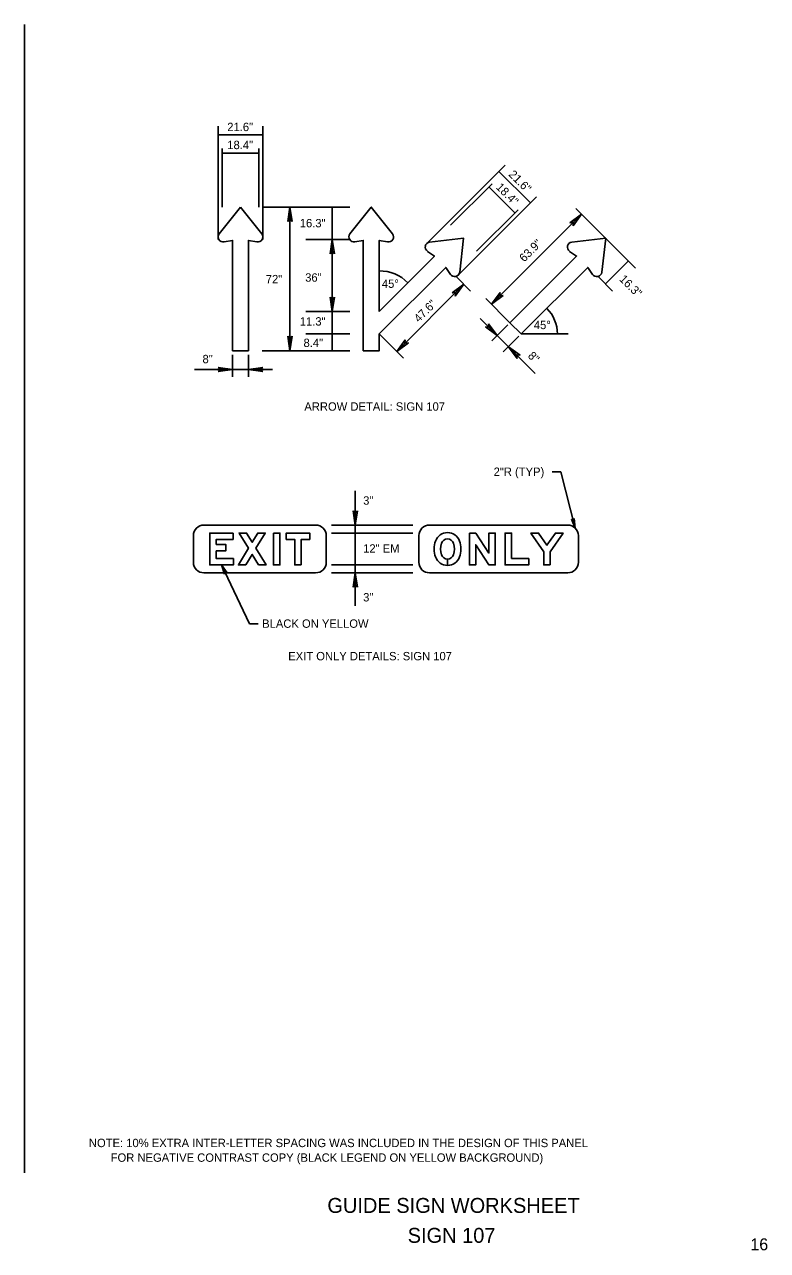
# Model space of a CAD drawing. Extents: x 531799 to 532094, y 1531149 to 1533620.
# Drawn here: x 531879.4 to 531932.2, y 1531151.4 to 1531238.5 of the extents above; entities that cross this region are included whole.
import ezdxf

# ---------------------------------------------------------------- set-up
doc = ezdxf.new("R2010")
doc.units = 0
for name, color, linetype in [('GSBWFill', 7, 'Continuous'), ('GSColorFill', 7, 'Continuous'), ('GSDims', 7, 'Continuous'), ('GSOutline', 7, 'Continuous'), ('LeaderLine_dp', 7, 'Continuous'), ('SheetBorder_dp', 7, 'Continuous'), ('SignPanel', 7, 'Continuous'), ('TextLabel', 7, 'Continuous'), ('TextMisc', 7, 'Continuous'), ('TextShtNo', 7, 'Continuous')]:
    doc.layers.add(name, color=color, linetype=linetype)

msp = doc.modelspace()

# ---------------------------------------------------------------- linework, layer by layer
at = {"layer": 'GSBWFill'}
for p, q in [((531892.157, 1531202.947), (531900.088, 1531202.947)), ((531917.996, 1531202.947), (531908.176, 1531202.947)), ((531891.401, 1531200.304), (531891.401, 1531202.192)), ((531900.844, 1531202.192), (531900.844, 1531200.304)), ((531907.421, 1531202.192), (531907.421, 1531200.304)), ((531918.751, 1531200.304), (531918.751, 1531202.192)), ((531909.458, 1531200.075), (531909.458, 1531200.528)), ((531909.458, 1531200.528), (531909.458, 1531200.075)), ((531900.088, 1531199.548), (531892.157, 1531199.548)), ((531908.176, 1531199.548), (531917.996, 1531199.548))]:
    msp.add_line(p, q, dxfattribs=at)
for points in [[(531894.227, 1531202.381), (531894.227, 1531201.928), (531893.026, 1531201.928), (531893.026, 1531201.565), (531893.705, 1531201.565), (531893.705, 1531201.112), (531893.026, 1531201.112), (531893.026, 1531200.568), (531894.249, 1531200.568), (531894.249, 1531200.115), (531892.572, 1531200.115), (531892.572, 1531202.381)], [(531896.039, 1531200.115), (531895.584, 1531200.859), (531895.129, 1531200.115), (531894.598, 1531200.115), (531895.319, 1531201.294), (531894.655, 1531202.381), (531895.186, 1531202.381), (531895.584, 1531201.729), (531895.982, 1531202.381), (531896.513, 1531202.381), (531895.85, 1531201.294), (531896.57, 1531200.115)], [(531897.094, 1531202.381), (531897.547, 1531202.381), (531897.547, 1531200.115), (531897.094, 1531200.115)], [(531899.061, 1531200.115), (531898.608, 1531200.115), (531898.608, 1531201.928), (531897.996, 1531201.928), (531897.996, 1531202.381), (531899.673, 1531202.381), (531899.673, 1531201.928), (531899.061, 1531201.928)], [(531911.012, 1531202.381), (531911.465, 1531202.381), (531912.394, 1531200.953), (531912.394, 1531202.381), (531912.847, 1531202.381), (531912.847, 1531200.115), (531912.399, 1531200.115), (531911.465, 1531201.55), (531911.465, 1531200.115), (531911.012, 1531200.115)], [(531914.003, 1531200.568), (531915.226, 1531200.568), (531915.226, 1531200.115), (531913.549, 1531200.115), (531913.549, 1531202.381), (531914.003, 1531202.381)], [(531916.748, 1531200.115), (531916.295, 1531200.115), (531916.295, 1531201.044), (531915.377, 1531202.381), (531915.926, 1531202.381), (531916.521, 1531201.515), (531917.116, 1531202.381), (531917.666, 1531202.381), (531916.748, 1531201.044)]]:
    msp.add_lwpolyline(points, close=True, dxfattribs=at)
for centre, radius, start, end in [((531892.157, 1531202.192), 0.755, 90, 180), ((531900.088, 1531202.192), 0.755, 0, 90), ((531908.176, 1531202.192), 0.755, 90, 180), ((531917.996, 1531202.192), 0.755, 0, 90), ((531909.458, 1531201.506), 0.906, 19.60625, 160.39375), ((531910.195, 1531201.244), 1.688, 160.39375, 199.60625), ((531910.195, 1531201.244), 1.235, 160.39375, 199.60625), ((531909.458, 1531201.506), 0.453, 19.60625, 160.39375), ((531908.722, 1531201.244), 1.235, 340.39375, 19.60625), ((531908.722, 1531201.244), 1.688, 340.39375, 19.60625), ((531892.157, 1531200.304), 0.755, 180, 270), ((531900.088, 1531200.304), 0.755, 270, 0), ((531908.176, 1531200.304), 0.755, 180, 270), ((531909.458, 1531200.982), 0.906, 199.60625, 270), ((531909.458, 1531200.982), 0.453, 199.60625, 270), ((531909.458, 1531200.982), 0.453, 270.01433, 340.39375), ((531909.458, 1531200.982), 0.906, 270.00716, 340.39375), ((531917.996, 1531200.304), 0.755, 270, 0)]:
    msp.add_arc(centre, radius, start, end, dxfattribs=at)
at = {"layer": 'GSColorFill'}
for p, q in [((531909.458, 1531200.075), (531909.458, 1531200.528)), ((531909.458, 1531200.528), (531909.458, 1531200.075))]:
    msp.add_line(p, q, dxfattribs=at)
for points in [[(531894.227, 1531202.381), (531894.227, 1531201.928), (531893.026, 1531201.928), (531893.026, 1531201.565), (531893.705, 1531201.565), (531893.705, 1531201.112), (531893.026, 1531201.112), (531893.026, 1531200.568), (531894.249, 1531200.568), (531894.249, 1531200.115), (531892.572, 1531200.115), (531892.572, 1531202.381)], [(531896.039, 1531200.115), (531895.584, 1531200.859), (531895.129, 1531200.115), (531894.598, 1531200.115), (531895.319, 1531201.294), (531894.655, 1531202.381), (531895.186, 1531202.381), (531895.584, 1531201.729), (531895.982, 1531202.381), (531896.513, 1531202.381), (531895.85, 1531201.294), (531896.57, 1531200.115)], [(531897.094, 1531202.381), (531897.547, 1531202.381), (531897.547, 1531200.115), (531897.094, 1531200.115)], [(531899.061, 1531200.115), (531898.608, 1531200.115), (531898.608, 1531201.928), (531897.996, 1531201.928), (531897.996, 1531202.381), (531899.673, 1531202.381), (531899.673, 1531201.928), (531899.061, 1531201.928)], [(531911.012, 1531202.381), (531911.465, 1531202.381), (531912.394, 1531200.953), (531912.394, 1531202.381), (531912.847, 1531202.381), (531912.847, 1531200.115), (531912.399, 1531200.115), (531911.465, 1531201.55), (531911.465, 1531200.115), (531911.012, 1531200.115)], [(531914.003, 1531200.568), (531915.226, 1531200.568), (531915.226, 1531200.115), (531913.549, 1531200.115), (531913.549, 1531202.381), (531914.003, 1531202.381)], [(531916.748, 1531200.115), (531916.295, 1531200.115), (531916.295, 1531201.044), (531915.377, 1531202.381), (531915.926, 1531202.381), (531916.521, 1531201.515), (531917.116, 1531202.381), (531917.666, 1531202.381), (531916.748, 1531201.044)]]:
    msp.add_lwpolyline(points, close=True, dxfattribs=at)
for centre, radius, start, end in [((531909.458, 1531201.506), 0.906, 19.60625, 160.39375), ((531910.195, 1531201.244), 1.688, 160.39375, 199.60625), ((531910.195, 1531201.244), 1.235, 160.39375, 199.60625), ((531909.458, 1531201.506), 0.453, 19.60625, 160.39375), ((531908.722, 1531201.244), 1.235, 340.39375, 19.60625), ((531908.722, 1531201.244), 1.688, 340.39375, 19.60625), ((531909.458, 1531200.982), 0.906, 199.60625, 270), ((531909.458, 1531200.982), 0.453, 199.60625, 270), ((531909.458, 1531200.982), 0.453, 270.01433, 340.39375), ((531909.458, 1531200.982), 0.906, 270.00716, 340.39375)]:
    msp.add_arc(centre, radius, start, end, dxfattribs=at)
at = {"layer": 'GSOutline'}
for points in [[(531894.227, 1531202.381), (531894.227, 1531201.928), (531893.026, 1531201.928), (531893.026, 1531201.565), (531893.705, 1531201.565), (531893.705, 1531201.112), (531893.026, 1531201.112), (531893.026, 1531200.568), (531894.249, 1531200.568), (531894.249, 1531200.115), (531892.572, 1531200.115), (531892.572, 1531202.381)], [(531896.039, 1531200.115), (531895.584, 1531200.859), (531895.129, 1531200.115), (531894.598, 1531200.115), (531895.319, 1531201.294), (531894.655, 1531202.381), (531895.186, 1531202.381), (531895.584, 1531201.729), (531895.982, 1531202.381), (531896.513, 1531202.381), (531895.85, 1531201.294), (531896.57, 1531200.115)], [(531897.094, 1531202.381), (531897.547, 1531202.381), (531897.547, 1531200.115), (531897.094, 1531200.115)], [(531899.061, 1531200.115), (531898.608, 1531200.115), (531898.608, 1531201.928), (531897.996, 1531201.928), (531897.996, 1531202.381), (531899.673, 1531202.381), (531899.673, 1531201.928), (531899.061, 1531201.928)], [(531911.012, 1531202.381), (531911.465, 1531202.381), (531912.394, 1531200.953), (531912.394, 1531202.381), (531912.847, 1531202.381), (531912.847, 1531200.115), (531912.399, 1531200.115), (531911.465, 1531201.55), (531911.465, 1531200.115), (531911.012, 1531200.115)], [(531914.003, 1531200.568), (531915.226, 1531200.568), (531915.226, 1531200.115), (531913.549, 1531200.115), (531913.549, 1531202.381), (531914.003, 1531202.381)], [(531916.748, 1531200.115), (531916.295, 1531200.115), (531916.295, 1531201.044), (531915.377, 1531202.381), (531915.926, 1531202.381), (531916.521, 1531201.515), (531917.116, 1531202.381), (531917.666, 1531202.381), (531916.748, 1531201.044)]]:
    msp.add_lwpolyline(points, close=True, dxfattribs=at)
for centre, radius, start, end in [((531909.458, 1531201.506), 0.906, 19.60625, 160.39375), ((531910.195, 1531201.244), 1.688, 160.39375, 199.60625), ((531910.195, 1531201.244), 1.235, 160.39375, 199.60625), ((531909.458, 1531201.506), 0.453, 19.60625, 160.39375), ((531908.722, 1531201.244), 1.235, 340.39375, 19.60625), ((531908.722, 1531201.244), 1.688, 340.39375, 19.60625), ((531909.458, 1531200.982), 0.906, 199.60625, 340.39375), ((531909.458, 1531200.982), 0.453, 199.60625, 340.39375)]:
    msp.add_arc(centre, radius, start, end, dxfattribs=at)
at = {"layer": 'LeaderLine_dp'}
for p, q in [((531893.165, 1531223.222), (531893.165, 1531231.279)), ((531896.334, 1531223.222), (531896.334, 1531231.279)), ((531893.165, 1531230.656), (531896.334, 1531230.656)), ((531893.447, 1531225.53), (531893.447, 1531229.697)), ((531893.447, 1531229.376), (531896.053, 1531229.376)), ((531896.053, 1531225.53), (531896.053, 1531229.697)), ((531907.848, 1531222.811), (531913.545, 1531228.509)), ((531913.105, 1531228.068), (531915.346, 1531225.827)), ((531909.68, 1531224.245), (531912.626, 1531227.191)), ((531912.399, 1531226.964), (531914.241, 1531225.121)), ((531902.506, 1531225.53), (531896.334, 1531225.53)), ((531898.107, 1531224.511), (531898.26, 1531225.53)), ((531898.26, 1531215.333), (531898.26, 1531225.53)), ((531898.26, 1531225.53), (531898.413, 1531224.511)), ((531901.268, 1531223.222), (531901.268, 1531225.53)), ((531910.089, 1531220.57), (531915.787, 1531226.268)), ((531898.26, 1531224.715), (531898.107, 1531224.511)), ((531898.413, 1531224.511), (531898.26, 1531224.715)), ((531911.522, 1531222.402), (531914.468, 1531225.348)), ((531912.584, 1531218.633), (531918.984, 1531225.032)), ((531918.155, 1531224.419), (531918.984, 1531225.032)), ((531918.984, 1531225.032), (531918.371, 1531224.203)), ((531918.578, 1531225.438), (531922.811, 1531221.205)), ((531918.407, 1531224.455), (531918.155, 1531224.419)), ((531918.371, 1531224.203), (531918.407, 1531224.455)), ((531902.506, 1531223.222), (531899.393, 1531223.222)), ((531901.115, 1531222.202), (531901.268, 1531223.222)), ((531901.268, 1531218.123), (531901.268, 1531223.222)), ((531901.268, 1531223.222), (531901.421, 1531222.202)), ((531901.268, 1531222.406), (531901.115, 1531222.202)), ((531901.421, 1531222.202), (531901.268, 1531222.406)), ((531920.672, 1531220.079), (531922.305, 1531221.711)), ((531910.089, 1531220.57), (531911.086, 1531219.573)), ((531920.181, 1531220.57), (531921.178, 1531219.573)), ((531905.846, 1531215.28), (531910.613, 1531220.047)), ((531909.783, 1531219.434), (531910.613, 1531220.047)), ((531910.036, 1531219.47), (531909.783, 1531219.434)), ((531910.613, 1531220.047), (531910, 1531219.218)), ((531910, 1531219.218), (531910.036, 1531219.47)), ((531912.584, 1531218.633), (531913.197, 1531219.462)), ((531913.197, 1531219.462), (531913.161, 1531219.209)), ((531901.268, 1531218.123), (531901.115, 1531219.143)), ((531901.115, 1531219.143), (531901.268, 1531218.939)), ((531901.268, 1531218.939), (531901.421, 1531219.143)), ((531901.421, 1531219.143), (531901.268, 1531218.123)), ((531912.179, 1531219.038), (531913.894, 1531217.323)), ((531913.414, 1531219.246), (531912.584, 1531218.633)), ((531913.161, 1531219.209), (531913.414, 1531219.246)), ((531902.506, 1531218.123), (531899.393, 1531218.123)), ((531901.268, 1531215.333), (531901.268, 1531218.123)), ((531911.777, 1531217.631), (531912.989, 1531216.418)), ((531912.412, 1531216.995), (531912.16, 1531217.031)), ((531912.16, 1531217.031), (531912.989, 1531216.418)), ((531912.989, 1531216.418), (531912.376, 1531217.248)), ((531912.376, 1531217.248), (531912.412, 1531216.995)), ((531912.613, 1531216.042), (531913.733, 1531217.163)), ((531898.26, 1531215.333), (531898.107, 1531216.353)), ((531898.107, 1531216.353), (531898.26, 1531216.149)), ((531898.26, 1531216.149), (531898.413, 1531216.353)), ((531898.413, 1531216.353), (531898.26, 1531215.333)), ((531902.506, 1531216.521), (531899.393, 1531216.521)), ((531904.604, 1531216.522), (531906.319, 1531214.806)), ((531905.846, 1531215.28), (531906.458, 1531216.109)), ((531906.458, 1531216.109), (531906.422, 1531215.857)), ((531912.989, 1531216.418), (531913.79, 1531215.617)), ((531913.414, 1531215.241), (531914.534, 1531216.361)), ((531914.695, 1531216.522), (531918.025, 1531216.522)), ((531894.183, 1531213.465), (531894.183, 1531215.049)), ((531895.316, 1531213.465), (531895.316, 1531215.049)), ((531902.506, 1531215.333), (531896.279, 1531215.333)), ((531906.675, 1531215.893), (531905.846, 1531215.28)), ((531906.422, 1531215.857), (531906.675, 1531215.893)), ((531913.79, 1531215.617), (531915.692, 1531213.715)), ((531913.79, 1531215.617), (531914.403, 1531214.788)), ((531914.619, 1531215.004), (531913.79, 1531215.617)), ((531914.403, 1531214.788), (531914.367, 1531215.04)), ((531914.367, 1531215.04), (531914.619, 1531215.004)), ((531894.183, 1531213.997), (531891.493, 1531213.997)), ((531893.367, 1531213.997), (531893.163, 1531214.15)), ((531893.163, 1531214.15), (531894.183, 1531213.997)), ((531894.183, 1531213.997), (531893.163, 1531213.844)), ((531893.163, 1531213.844), (531893.367, 1531213.997)), ((531895.316, 1531213.997), (531894.183, 1531213.997)), ((531895.316, 1531213.997), (531896.336, 1531214.15)), ((531897.03, 1531213.997), (531895.316, 1531213.997)), ((531896.336, 1531213.844), (531895.316, 1531213.997)), ((531896.336, 1531214.15), (531896.132, 1531213.997)), ((531896.132, 1531213.997), (531896.336, 1531213.844)), ((531902.902, 1531205.367), (531902.902, 1531202.947)), ((531902.902, 1531202.947), (531902.749, 1531203.967)), ((531902.749, 1531203.967), (531902.902, 1531203.763)), ((531902.902, 1531203.763), (531903.055, 1531203.967)), ((531903.055, 1531203.967), (531902.902, 1531202.947)), ((531901.212, 1531202.947), (531906.993, 1531202.947)), ((531902.902, 1531202.947), (531902.902, 1531199.548)), ((531918.396, 1531203.253), (531918.264, 1531203.36)), ((531918.264, 1531203.36), (531918.53, 1531202.726)), ((531918.462, 1531203.41), (531918.396, 1531203.253)), ((531918.53, 1531202.726), (531918.462, 1531203.41)), ((531901.212, 1531202.381), (531906.993, 1531202.381)), ((531893.411, 1531200.115), (531893.793, 1531199.543)), ((531893.608, 1531199.456), (531893.411, 1531200.115)), ((531893.642, 1531199.623), (531893.608, 1531199.456)), ((531893.793, 1531199.543), (531893.642, 1531199.623)), ((531901.212, 1531200.115), (531906.993, 1531200.115)), ((531901.212, 1531199.548), (531906.993, 1531199.548)), ((531902.749, 1531198.528), (531902.902, 1531199.548)), ((531902.902, 1531199.548), (531902.902, 1531197.197)), ((531902.902, 1531199.548), (531903.055, 1531198.528)), ((531902.902, 1531198.732), (531902.749, 1531198.528)), ((531903.055, 1531198.528), (531902.902, 1531198.732))]:
    msp.add_line(p, q, dxfattribs=at)
for centre, radius, start, end in [((531904.603, 1531218.123), 2.884, 45, 90), ((531914.695, 1531216.522), 2.569, 360, 45)]:
    msp.add_arc(centre, radius, start, end, dxfattribs=at)
at = {"layer": 'SheetBorder_dp'}
msp.add_line((531879.408, 1531238.504), (531879.408, 1531156.924), dxfattribs=at)
at = {"layer": 'SignPanel'}
for p, q in [((531893.235, 1531223.627), (531894.75, 1531225.53)), ((531894.75, 1531225.53), (531896.264, 1531223.627))]:
    msp.add_line(p, q, dxfattribs=at)
for points in [[(531905.551, 1531223.627), (531904.036, 1531225.53), (531902.522, 1531223.627)], [(531895.908, 1531223.058), (531895.316, 1531223.166), (531895.316, 1531215.333), (531894.183, 1531215.333), (531894.183, 1531223.166), (531893.591, 1531223.058)], [(531902.878, 1531223.058), (531903.47, 1531223.166), (531903.47, 1531215.333), (531904.603, 1531215.333), (531904.603, 1531216.521), (531909.33, 1531221.248), (531909.672, 1531220.753)], [(531904.603, 1531218.123), (531904.603, 1531223.166), (531905.195, 1531223.058)], [(531910.327, 1531220.904), (531910.601, 1531223.321), (531908.185, 1531223.046)], [(531918.277, 1531223.046), (531920.693, 1531223.321), (531920.418, 1531220.904)], [(531908.034, 1531222.391), (531908.529, 1531222.049), (531904.603, 1531218.123)], [(531913.894, 1531217.323), (531918.621, 1531222.049), (531918.126, 1531222.391)], [(531919.764, 1531220.753), (531919.422, 1531221.248), (531914.695, 1531216.522), (531913.894, 1531217.323)]]:
    msp.add_lwpolyline(points, dxfattribs=at)
for centre, start, end in [((531893.526, 1531223.413), 143.69808, 280.32959), ((531895.973, 1531223.413), 259.67041, 36.30192), ((531902.813, 1531223.413), 143.69808, 280.32959), ((531905.259, 1531223.413), 259.67041, 36.30192), ((531908.24, 1531222.689), 98.69808, 235.32959), ((531918.331, 1531222.689), 98.69808, 235.32959), ((531909.969, 1531220.959), 214.67041, 351.30192), ((531920.061, 1531220.959), 214.67041, 351.30192)]:
    msp.add_arc(centre, 0.361, start, end, dxfattribs=at)
at = {"layer": 'TextLabel'}
for p, q in [((531916.896, 1531206.722), (531917.516, 1531206.722)), ((531918.53, 1531202.726), (531917.516, 1531206.722)), ((531893.411, 1531200.115), (531895.379, 1531195.933)), ((531895.999, 1531195.933), (531895.379, 1531195.933))]:
    msp.add_line(p, q, dxfattribs=at)

# ---------------------------------------------------------------- texts
at = {"layer": 'GSDims'}
for s, p in [('21.6"', (531893.812, 1531230.932)), ('18.4"', (531893.812, 1531229.652)), ('16.3"', (531898.961, 1531224.097)), ('72"', (531896.549, 1531220.12)), ('36"', (531899.346, 1531220.235)), ('45°', (531904.795, 1531219.795)), ('11.3"', (531898.961, 1531217.116)), ('45°', (531915.59, 1531216.865)), ('8.4"', (531899.228, 1531215.594)), ('8"', (531892.052, 1531214.442)), ('3"', (531903.464, 1531204.391)), ('12" EM', (531903.464, 1531200.985)), ('3"', (531903.464, 1531197.519))]:
    msp.add_text(s, height=0.595, dxfattribs=at).set_placement(p)
for s, rotation, p in [('21.6"', 315, (531913.757, 1531227.806)), ('18.4"', 315, (531912.852, 1531226.9)), ('63.9"', 45, (531914.909, 1531221.591)), ('16.3"', 315, (531921.618, 1531220.372)), ('47.6"', 45, (531907.424, 1531217.296)), ('8"', 315, (531915.121, 1531214.915))]:
    msp.add_text(s, height=0.595, rotation=rotation, dxfattribs=at).set_placement(p)
at = {"layer": 'TextLabel'}
for s, p in [('ARROW DETAIL: SIGN 107', (531899.286, 1531211.069)), ('BLACK ON YELLOW', (531896.288, 1531195.647)), ('EXIT ONLY DETAILS: SIGN 107', (531898.141, 1531193.336)), ('NOTE: 10% EXTRA INTER-LETTER SPACING WAS INCLUDED IN THE DESIGN OF THIS PANEL', (531883.982, 1531158.753)), ('       FOR NEGATIVE CONTRAST COPY (BLACK LEGEND ON YELLOW BACKGROUND)', (531883.982, 1531157.712))]:
    msp.add_text(s, height=0.595, dxfattribs=at).set_placement(p)
msp.add_text('2"R (TYP)', height=0.595, rotation=360, dxfattribs=at).set_placement((531912.732, 1531206.436))
at = {"layer": 'TextMisc'}
for s, p in [('  GUIDE SIGN WORKSHEET  ', (531900.133, 1531154.079)), ('        SIGN 107        ', (531903.468, 1531151.954))]:
    msp.add_text(s, height=1.0625, rotation=360, dxfattribs=at).set_placement(p)
at = {"layer": 'TextShtNo'}
msp.add_text('16', height=0.85, rotation=360, dxfattribs=at).set_placement((531930.972, 1531151.423))

doc.saveas('drawing.dxf')
